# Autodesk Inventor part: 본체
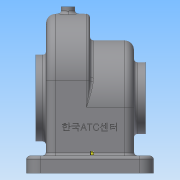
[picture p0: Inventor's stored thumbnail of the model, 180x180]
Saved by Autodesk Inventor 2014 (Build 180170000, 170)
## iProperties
Created: 2017-11
Part Number: 본체
Material: 일반
Document SubType Name: Modeling
Designer: net
Density: 1 g/cm^3
Appearance: 기본값
Author: net
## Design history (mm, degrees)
sketch "스케치1"
  geometry: L1 (-55, 75)-(55, 75); L2 (55, 75)-(55, -75); L3 (55, -75)-(-55, -75); L4 (-55, -75)-(-55, 75); 3 further points
  constraints: 8 end point, 2 midpoint, 2 parallel, 1 horizontal, 1 horizontal alignment, 1 perpendicular, 1 vertical alignment
  dimensions: "d0" = 110 distance of L1.start L1.end; "d1" = 150 distance of L3.end L1.start
extrude "돌출1" new body sketch "스케치1" distance "d2" = 15; taper "d3" = 0 deg
fillet "모깎기1" dims "d4" = 12
hole "구멍1" diameter "d7" = 5; stored, may be unused: countersink angle "d11" = 90 deg, drill point angle "d13" = 118 deg; dims "d5" = 10, "d6" = 10, "d8" = 6, "d9" = 12, "d10" = 5, "d12" = 8
hole "구멍2" diameter "d16" = 5; stored, may be unused: countersink angle "d20" = 90 deg, drill point angle "d22" = 118 deg; dims "d14" = 10, "d15" = 10, "d17" = 6, "d18" = 12, "d19" = 5, "d21" = 8
node "작업 평면1"
sketch "스케치3"
  geometry: L1 (5, 80)-(121, 80); L2 (121, 80)-(121, 15); L3 (121, 15)-(5, 15); L4 (5, 15)-(5, 80); L5 (126, 15)-(0, 15) reference; L6 (0, 15)-(0, 0) reference; L7 (126, 15)-(0, 15) reference; L8 (126, 0)-(126, 15) reference; L9 (0, 0)-(126, 0) reference; 4 further points
  constraints: 8 end point, 3 midpoint, 2 parallel, 1 collinear, 1 horizontal, 1 horizontal alignment, 1 perpendicular, 1 vertical alignment, 2 other
  dimensions: "d24" = 116 distance between parallel lines of L2 L4; "d25" = 80 distance between parallel lines of L9 L1
extrude "돌출2" join sketch "스케치3" distance "d26" = 38; taper "d27" = 0 deg
node "작업 평면2"
sketch "스케치4"
  geometry: L1 (15, 121)-(15, 5) reference; L2 (0, 126)-(0, 0) reference; L3 (57, 121)-(15, 121); L4 (15, 121)-(15, 5); L5 (15, 5)-(57, 5); L6 (57, 5)-(57, 121); A1 r 58 centre (57, 63) between (57, 5) and (57, 121); 2 further points
  constraints: 8 end point, 2 midpoint, 2 parallel, 2 point on circle, 1 centre point, 1 collinear, 1 horizontal, 1 horizontal alignment, 1 perpendicular
  dimensions: "d30" = 58 radius of A1; "d31" = 57 distance between parallel lines of L2 L6
extrude "돌출3" join sketch "스케치4" distance "d32" = 38; taper "d33" = 0 deg
sketch "스케치5" dims "d34" = 106
  geometry: L1 (5, 15)-(5, 57) reference; L2 (121, 57)-(121, 15) reference; L3 (10, 57)-(116, 57); L4 (116, 57)-(116, 0); L5 (116, 0)-(10, 0); L6 (10, 0)-(10, 57); L7 (0, 0)-(126, 0) reference; A1 r 58 centre (63, 57) between (121, 57) and (5, 57) reference; 2 further points
  constraints: 8 end point, 2 parallel, 1 coincident, 1 collinear, 1 horizontal, 1 horizontal alignment, 1 midpoint, 1 perpendicular, 2 other
extrude "돌출4" cut sketch "스케치5" distance "d35" = 33; taper "d36" = 0 deg
sketch "스케치6" dims "d37" = 106
  geometry: L1 (126, 0)-(0, 0) reference; L2 (5, 80)-(5, 15) reference; L3 (121, 15)-(5, 15) reference; L4 (121, 15)-(121, 80) reference; L5 (5, 80)-(5, 15) reference; L6 (10, 80)-(116, 80); L7 (116, 80)-(116, 0); L8 (116, 0)-(10, 0); L9 (10, 0)-(10, 80); A1 r 58 centre (63, 80) between (121, 80) and (5, 80) reference; A2 r 58 centre (63, 80) between (121, 80) and (5, 80) reference; 3 further points
  constraints: 8 end point, 2 midpoint, 2 parallel, 1 coincident, 1 collinear, 1 horizontal, 1 horizontal alignment, 1 perpendicular, 1 vertical alignment, 2 other
extrude "돌출5" cut sketch "스케치6" distance "d38" = 33; taper "d39" = 0 deg
sketch "스케치7"
  geometry: L1 (121, 80)-(121, 57); L2 (5, 57)-(5, 80); L3 (9.755, 80)-(10, 80); L4 (116, 80)-(116.245, 80); L5 (5, 57)-(10, 57); L6 (116, 57)-(121, 57); A1 r 58 centre (63, 80) between (121, 80) and (5, 80) reference; A2 r 53 centre (63, 80) between (116, 80) and (10, 80) reference; A3 r 58 centre (63, 80) between (121, 80) and (5, 80); A4 r 58 centre (63, 57) between (121, 57) and (5, 57) reference; A5 r 53 centre (63, 57) between (116, 57) and (10, 57) reference; A6 r 53 centre (63, 57) between (116, 57) and (10, 57); 1 further point
  constraints: 12 end point, 10 point on circle, 4 perpendicular, 2 centre point, 2 coincident, 2 concentric, 2 horizontal, 1 parallel, 1 tangent
  dimensions: "d96" = 23 distance between parallel lines of L6 L4; "d97" = 23 distance between parallel lines of L6 L3
extrude "돌출6" join sketch "스케치7" distance "d43" = 5; taper "d44" = 0 deg
sketch "스케치8"
  geometry: L1 (126, 0)-(0, 0) reference; C1 r 37.5 at (63, 65); C2 r 16 at (63, 65); 2 further points
  constraints: 2 centre point, 1 coincident, 1 midpoint, 1 vertical alignment
  dimensions: "d45" = 65 distance from line of L1 C1.centre; "d46" = 75 diameter of C1; "d47" = 32 diameter of C2
extrude "돌출7" join sketch "스케치8" distance "d48" = 9; taper "d49" = 0 deg
extrude "돌출8" cut sketch "스케치8" stored distance "d50" = 9; taper "d51" = 0 deg
sketch "스케치9" dims "d52" = 58
  geometry: C1 r 16 at (0, 0) reference; C2 r 37.5 at (0, 0) reference; 3 further points
  constraints: 2 vertical alignment, 1 coincident, 2 other
hole "구멍3" sketch "스케치9" at (0, 29) diameter "d53" = 2.459; stored, may be unused: countersink angle "d57" = 90 deg, drill point angle "d59" = 118 deg; dims "d54" = 6, "d55" = 12, "d56" = 5, "d58" = 8
sketch "스케치10" dims "d64" = 52
  geometry: C1 r 16 at (-63, 65) reference; C2 r 31 at (-63, 65); 3 further points
  constraints: 2 coincident, 2 vertical alignment, 1 centre point, 2 other
  dimensions: "d63" = 62 diameter of C2
extrude "돌출9" join sketch "스케치10" distance "d65" = 10; taper "d66" = 0 deg
sketch "스케치11" dims "d67" = 52
  geometry: C1 r 16 at (0, 0) reference; C2 r 31 at (0, 0) reference; 3 further points
  constraints: 2 vertical alignment, 1 coincident, 2 other
hole "구멍4" sketch "스케치11" at (0, 26) diameter "d68" = 2.459; stored, may be unused: countersink angle "d72" = 90 deg, drill point angle "d74" = 118 deg; dims "d69" = 6, "d70" = 12, "d71" = 5, "d73" = 8
node "작업 평면3"
sketch "스케치12"
  geometry: L1 (38, -58)-(38, 58) reference; L2 (0, 58)-(0, -58) reference; C1 r 6 at (19, 0); 3 further points
  constraints: 2 midpoint, 1 centre point, 1 coincident, 1 horizontal alignment
  dimensions: "d79" = 19 distance from line of L1 C1.centre; "d80" = 12 diameter of C1
extrude "돌출10" join sketch "스케치12" stored distance "d81" = 10; taper "d82" = 0 deg
hole "구멍5" diameter "d85" = 4.134; stored, may be unused: countersink angle "d89" = 90 deg, drill point angle "d91" = 118 deg; dims "d86" = 6, "d87" = 12, "d88" = 5, "d90" = 44, "d108" = 10, "d109" = 10
chamfer "모따기1" distance "d92" = 1; stored, may be unused: second distance "d93" = 2, angle "d94" = 45 deg
fillet "모깎기2" dims "d95" = 8
extrude "돌출11" join sketch "스케치7" distance "d98" = 5; taper "d99" = 0 deg
fillet "모깎기3" dims "d100" = 3
fillet "모깎기4" dims "d101" = 3
fillet "모깎기5" dims "d102" = 3
fillet "모깎기6" dims "d103" = 3
sketch "스케치13"
  geometry: L1 (-8, 62)-(-8, 0) reference; L2 (73, -18)-(-13, -18) reference; 2 further points
  constraints: 1 other
  dimensions: "d104" = 38 distance from line of L1 point (30, 22); "d105" = 40 distance from line of L2 point (30, 22)
feature "엠보싱1" sketch "스케치13" dims "d106" = 0.5, "d107" = 0
node "솔리드1"
mirror "대칭1"
pattern_circular "원형 패턴1" dims angle "d61" = 360 deg
pattern_circular "원형 패턴2" dims angle "d76" = 360 deg
node "투영된 루프1"
node "투영된 루프2"
other parameters: "d23" = -55, "d28" = -55, "d29" = 116, "d78" = -144
